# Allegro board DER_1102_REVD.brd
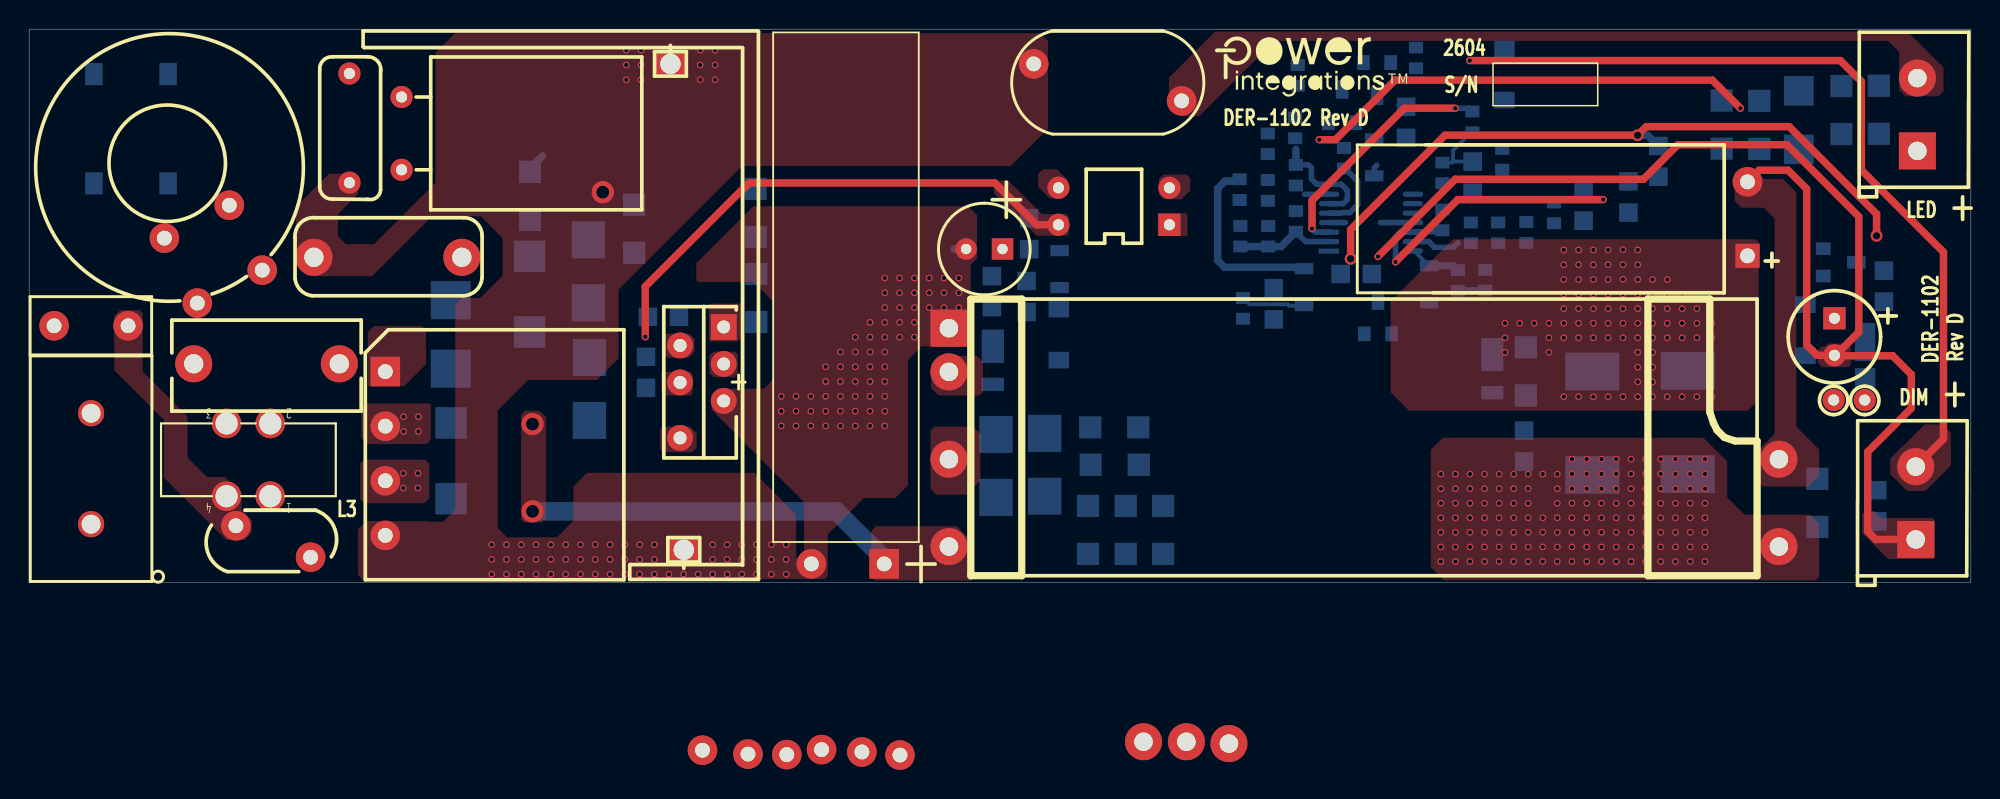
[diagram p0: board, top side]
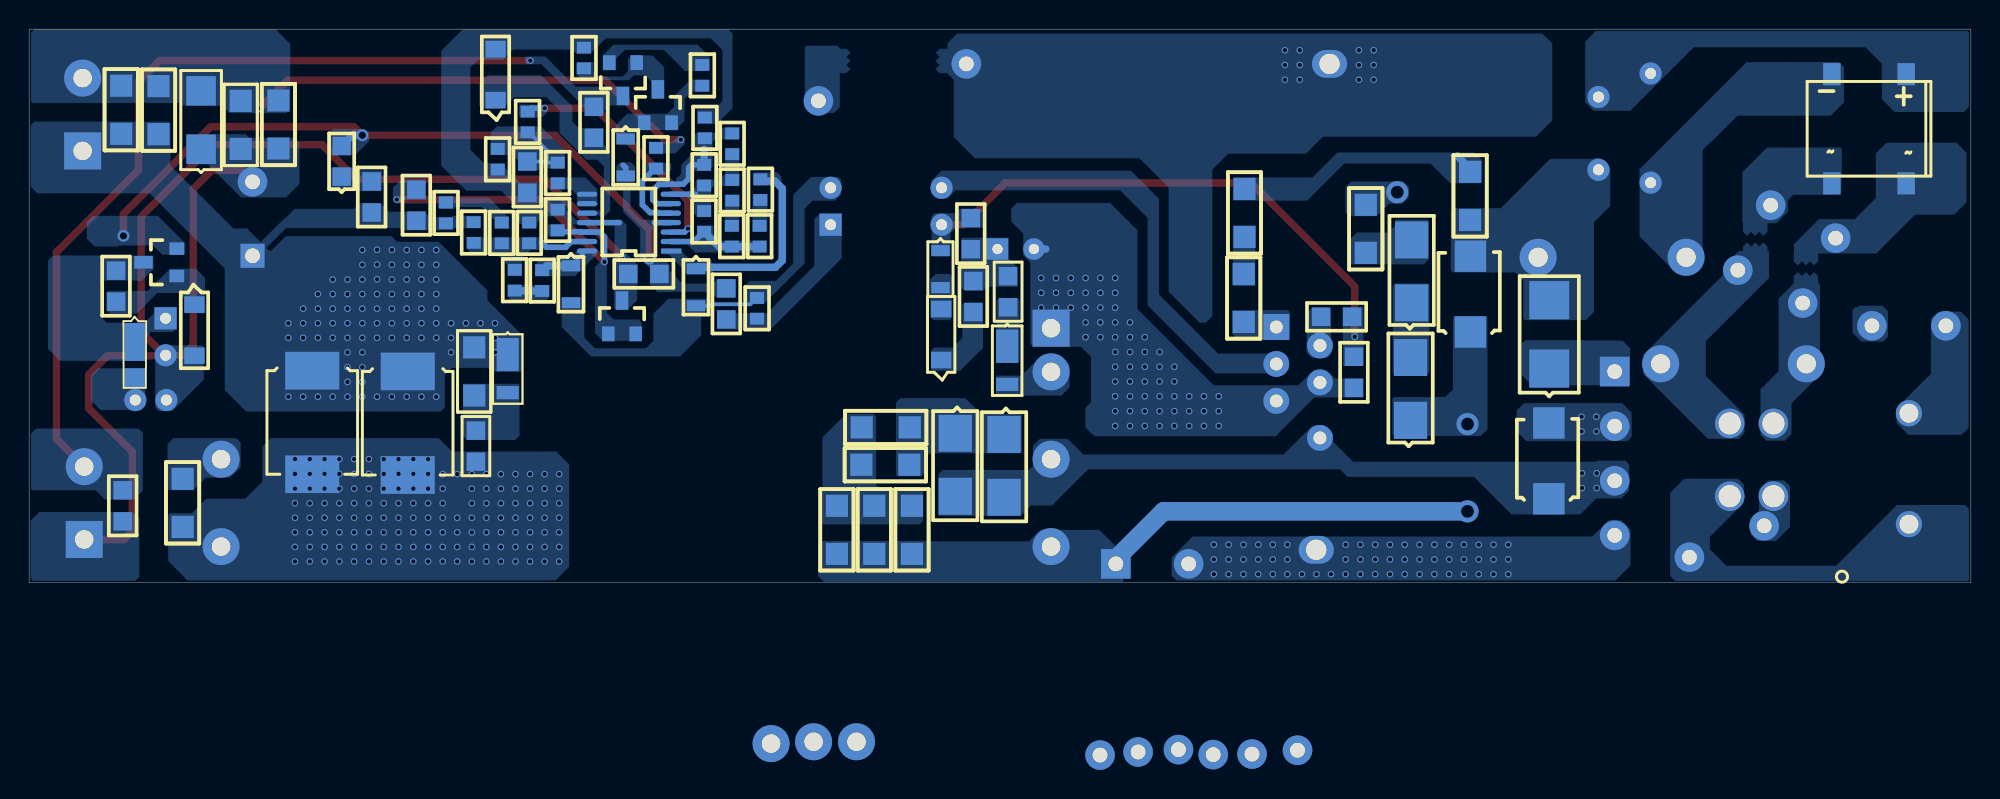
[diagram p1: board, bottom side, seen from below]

Outline 133.35 x 38 mm; copper layers: TOP, BOTTOM. Coordinates in mm from the lower left corner of the outline.
Outline path: 0,38 0,0 133.35,0 133.35,38 0,38

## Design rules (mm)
constraint set DEFAULT: min track width 0.508

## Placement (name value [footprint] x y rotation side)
BR1  MSB30M-13  [PISMD_4SMD_DI]  7 31.15 0 bottom
C1  220 pF  [PISMC0805]  102.67 8.29 90 bottom
C2  1000 pF  [PISMC1206]  72.72 1.96 90 bottom
C3  330 uF  [PIPOLCAPCLYD10MM040]  118.01 22.43 90 top
C5  15 uF  [PIPOLCAPCLYD10X35D040]  53.72 1.27 0 top
C7  68 nF  [PI_NP_CAP_RAD9P8X4P2X7P5X0P6]  22 34.95 270 top
C8  22 uf  [PIPOLCAPCLYD248LS098028]  65.6 22.89 180 top
C9  220 nF  [PI_NP_CAP_RAD470X220LS400D40]  29.72 22.33 180 top
C10  0.47 uF  [PISMC0805]  42.37 15.49 270 bottom
C11  2.2 nF  [PINPYCAPRAD540X290LS400040]  68.99 35.61 0 top
C15  100 uF  [PIPOLCAPCYLD250LS100030]  123.98 18.14 270 top
C21  10 uF  [PISMC0805]  90.07 21.18 0 bottom
C30  1 uF  [PISMC0603]  83.13 26.26 90 bottom
C31  100 pF  [PISMC0603]  85.06 30.84 270 bottom
C33  4.7 uF  [PISMC0805]  99.14 26.77 90 bottom
C35  1000 pF  [PISMC0603]  85.09 24.49 270 bottom
C37  1000 pF  [PISMC0805]  126.92 4.19 90 bottom
C38  10 uF  [PISMC1206]  127.03 34.11 270 bottom
C39  1 uF  [PISMC0603]  97.05 25.6 270 bottom
C40  100 pF  [PISMC0603]  100.89 24.71 270 bottom
C41  22 nF  [PISMC0603]  98.12 20.02 90 bottom
C42  10 uF  [PISMC1206]  124.46 34.09 270 bottom
C43  100 pF  [PISMC1206]  122.81 3.81 90 bottom
CX1  0.15 uF  [PINPXCAPRAD13X6MM040]  11.3 15.01 0 top
D1  PU6JB  [PISMSMB]  34.37 17.2 90 bottom
D2  HS5F  [PISMDO214AB12]  107.35 14.49 270 bottom
D3  HS5F  [PISMDO214AB12]  113.91 14.54 270 bottom
D4  USB260HM3/52T  [PISMDO214AA12]  28.96 14.68 90 bottom
D5  DFLR1200-7  [PISMDDFLR120012]  66.18 16.24 90 bottom
D7  GS1M-LTP  [PISMDO214AC12]  66.4 10.16 270 bottom
D8  GS1M-LTP  [PISMDO214AC12]  69.75 10.24 270 bottom
D9  PU6JB  [PISMSMB]  28.98 5.74 90 bottom
D10  US1B  [PISMDSMA]  121.54 29.74 90 bottom
D11  BAV19WS  [PISMSOD323]  70.76 22.78 270 bottom
D13  BAV16WS-7-F  [PISMSOD323]  87.55 21.54 270 bottom
D14  SS10200HE_R1_00001  [PI_SM_SOD-123HE]  126.09 16.51 270 bottom
D15  SD103CWS-E3-08  [PISMSOD323]  92.38 30.45 270 bottom
D16  BAV16WS-7-F  [PISMSOD323]  96.14 21.74 270 bottom
D17  DFLR1200-7  [PISMDDFLR120012]  100.48 15.67 90 bottom
D18  1N4148WS  [PISMDSOD323]  111.89 27.86 90 bottom
F1  3.15 A  [PI_RST_MICROFUSE]  1.72 17.62 0 top
FL1  Hole_30mils  [PI_HOLE_30MIL]  126.06 12.52 0 top
FL2  Hole_30mils  [PI_HOLE_30MIL]  123.93 12.52 0 top
HS_POST1  HS_Post  [PI_HSK_POST]  44.04 35.61 180 top
HS_POST2  HS_Post  [PI_HSK_POST]  44.96 2.24 0 top
J1  TERMINAL BLOCK  [PI_TERM_BLOCK_2PIN_LS200]  129.68 29.63 0 top
J2  CON2  [CONN_1707027_PXC]  4.26 4 90 top
J11  TERMINAL BLOCK  [PI_TERM_BLOCK_2PIN_LS200]  129.57 2.95 0 top
L1  22 mH  [PI_IND_4P_21P5X11MMD041]  9.48 28.79 26.9 top
L2  1 mH  [PICHOKE10P5X14P5D030]  25.58 30.84 270 top
L3  250 uH  [PI_TOROID_CMC4P_V_DER1094]  16.56 5.92 180 top
L4  80 ohm  [PISMR0805]  42.49 18.24 0 bottom
NOREF  -  []  0 38 0 top
NOREF#2  -  []  81.46 37.92 0 top
NOREF#3  -  []  0 0 90 top
Q5  MMBT3906  [PISMSOT23123_1]  92.56 34.59 0 bottom
Q7  FMMT491  [PISMSOT23123_1]  124.31 21.97 90 bottom
R1  100  [PISMR1206]  102.79 12.84 90 bottom
R2  1 M  [PISMR1206]  75.31 1.96 90 bottom
R3  1 M  [PISMR1206]  77.88 1.96 90 bottom
R4  2.40 M  [PISMR1206]  34.39 24.89 90 bottom
R7  20  [PISMR1206]  76.17 10.64 180 bottom
R8  20  [PISMR1206]  76.2 8.08 180 bottom
R9  10  [PISMR0805]  66.12 18.9 90 bottom
R10  6.98 k  [PISMR0805]  68.68 22.89 90 bottom
R13  2.7 M  [PISMR1206]  49.94 21.18 270 bottom
R16  0.2  [PISMR1206]  118.82 29.77 90 bottom
R27  2.40 M  [PISMR1206]  49.89 27.03 270 bottom
R28  270  [PISMR0805]  68.5 18.57 90 bottom
R33  1 k  [PISMR0603]  90.3 29.84 270 bottom
R34  1 k  [PISMR0603]  86.94 30.51 90 bottom
R35  86.6 k  [PISMR0603]  87 27.25 90 bottom
R36  15 k  [PISMR0603]  83.19 23.06 90 bottom
R37  12.1 k  [PISMR0603]  87 25.5 270 bottom
R39  10 k  [PISMR0603]  99.11 32.33 270 bottom
R40  7.5 k  [PISMR0603]  95.25 35.31 90 bottom
R41  6.34 k  [PISMR0603]  87.12 34.11 90 bottom
R42  20 k  [PISMR0805]  94.56 30.53 90 bottom
R47  1 k  [PISMR1206]  41.55 22.63 90 bottom
R48  3.3 k  [PISMR0805]  127.38 21.41 270 bottom
R49  1 k  [PISMR0805]  85.47 20.19 270 bottom
R57  47.5 k  [PISMR0805]  106.76 24.84 90 bottom
R59  0.2  [PISMR1206]  116.23 29.79 90 bottom
R60  1 k  [PISMR0603]  85.06 27.64 270 bottom
R62  15 k  [PISMR0603]  99.01 23.29 90 bottom
R63  10 k  [PISMR0603]  104.72 24.66 90 bottom
R64  205 k  [PISMR0603]  102.82 24.74 270 bottom
R65  249 k  [PISMR0603]  100 21.46 270 bottom
R66  20 k  [PISMR0603]  97.05 28.83 270 bottom
R67  3.32 k  [PISMR0603]  83.36 18.11 90 bottom
R68  100  [PISMR0805]  109.83 25.4 90 bottom
R69  3 M  [PISMR0603]  101.17 29.77 270 bottom
RV1  300 Vac  [PIDISC350X160LS210X140040]  13.64 4.55 0 top
T1  EDR4110  [PI_BOBBIN_EDR4110_9P_6X3]  91.67 9.96 0 top
T2  EPC17  [PI_BOBBIN_EPC17_4X6_10P]  24.46 14.48 0 top
U1  LTV817A  [PI_DIP4]  78.31 24.56 90 top
U2  TNY5075E  [PIICESIP76TH]  47.7 17.54 270 top
U4  ADA4522-4ARUZ-RL  [PI_SM_14TSSOP]  89.28 22.76 90 bottom
U6  LMV431AIMF  [PISMSOT23132]  89.23 31.57 180 bottom
U9  LM431BIM3/NOPB  [PISMSOT23123]  91.69 17.07 180 bottom
VR2  MMSZ5241C-E3-08  [PI_SM_SOD-123_12]  70.71 15.27 90 bottom
VR3  BZG04-200-HM3-08  [PISMDO214AC12]  38.48 11.13 90 bottom
VR4  BZG04-200-HM3-08  [PISMDO214AC12]  38.4 19.2 90 bottom
VR6  MMSZ5242B-7-F  [PI_SM_SOD-123_12]  101.32 33.12 90 bottom
VR7  MMSZ5242B-7-F  [PI_SM_SOD-123_12]  122 19.08 270 bottom

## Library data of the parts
BR1 = DIODE BRIDGE_+~-~
C1 C10 C21 C33 C37 = CAP NP: alternate symbols: (Unisem_RMCF0805UL)
C2 C7 = CAP NP
C3 = CAP POL: alternate symbols: (pipolcapcyld400ls2000401000h)
C5 = CAP POL: alternate symbols: (pipolcapclyd10x35D040H)
C8 = CAP POL: alternate symbols: (pipolcapclyd248ls098028_h)
C9 = CAP NP: alternate symbols: (pi_np_cap_rad470x220ls400d40_h)
C11 = CAP NP: alternate symbols: (pinpycaprad540x290ls400040h)
C15 = CAP POL: alternate symbols: (pipolcapcyld250ls100030h)
C30 = CAP NP: alternate symbols: (Unisem_RMCF0603UL,pismc0603_1)
C31 C39 C41 = CAP NP: alternate symbols: (Unisem_RMCF0603UL)
C35 C40 = CAP NP: alternate symbols: (Unisem_RMCF0603UL); room: 3
C38 C42 = CAP NP: alternate symbols: (pismc1206_1)
C43 = CAP NP: room: 3
CX1 = CAP NP: alternate symbols: (pinpxcaprad13x6x12Hmm040)
D1-D5 D7-D11 D17 D18 = DIODE
D13 D16 = DIODE: alternate symbols: (SOD323_UL_IPC,pismsod323_1)
D14 = DIODE SCHOTTKY
D15 = DIODE SCHOTTKY: alternate symbols: (SOD323_UL_IPC,pismsod323_1)
F1 = FUSE: alternate symbols: (pirstmicrofusehoz)
FL1 FL2 = FlyingLead: room: 3
HS_POST1 HS_POST2 = HS_POST
J1 J11 = CON2
J2 = CON2: User Part Number: PN; Tolerance: TOL
L1 = CMC_ 4P_12_34: alternate symbols: (pi_ind_4p_21p5x11mmd041H)
L2 = INDUCTOR: alternate symbols: (pichoke10p5x14p5d030H)
L3 = TORRID 4P_12_43a: alternate symbols: (pi_torid_CMC4p_H)
L4 = INDUCTOR_BEAD_2
Q5 = PNP_BEC
Q7 = NPN_BEC
R1-R4 R7 R8 R13 R16 R27 R47 R59 = R
R9 R10 R28 R42 R48 R49 R68 = R: alternate symbols: (Unisem_RMCF0805UL)
R33-R37 R39-R41 R64-R66 = R: alternate symbols: (Unisem_RMCF0603UL)
R57 = R: alternate symbols: (Unisem_RMCF0805UL); room: 3
R60 R62 R63 R67 R69 = R: alternate symbols: (Unisem_RMCF0603UL); room: 3
RV1 = VARISTOR: alternate symbols: (pi_disc_354x220_ls220x10_040_h,pidisc350x160ls210x140040SF)
T1 = BEQ20_9P
T2 = BEPC_17_10P
U1 = OPTO_A_B
U2 = TinySwitch-5E
U4 = TL084_Hetero
U6 = TL431/SOT-23_RCA
U9 = TL431/SOT-23_CAR
VR2-VR4 VR6 VR7 = DIODE_ZENER

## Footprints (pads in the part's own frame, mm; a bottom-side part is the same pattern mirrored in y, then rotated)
CONN_1707027_PXC
  round 1.803 hole 1.295: 1(0,0) 2(7.62,0)
PI_BOBBIN_EDR4110_9P_6X3
  rect 2.54x2.54 hole 1.27: 1(-28.5,7.5)
  round 2.54 hole 1.27: 2(-28.5,4.5) 3(-9.271,-21.031) 4(-28.5,-1.5) 5(-15.138,-20.904) 6(-28.5,-7.5) 7(28.5,-7.5) 8(-12.192,-20.904) 9(28.5,-1.5)
PI_BOBBIN_EPC17_4X6_10P
  rect 2.032x2.032 hole 1.016: 1(0,0)
  round 2.032 hole 1.016: 2(0,-3.75) 3(0,-7.5) 4(0,-11.25) 5(35.346,-26.342) 6(32.73,-26.128) 7(29.961,-25.964) 8(27.573,-26.309) 9(24.906,-26.273) 10(21.782,-26.008)
PI_DIP4
  rect 1.524x1.524 hole 0.762: 1(0,0)
  round 1.524 hole 0.762: 2(2.54,0) 3(2.54,7.62) 4(0,7.62)
PI_HOLE_30MIL
  round 1.524 hole 0.762: 1(0,0)
PI_HSK_POST
  oval 2.413x1.905 hole 1.397: 1(0,0)
PI_IND_4P_21P5X11MMD041
  round 2.032 hole 1.016: 1(-2.5,-4.5) 2(-2.5,-9.5) 3(2.5,-4.5) 4(2.5,-9.5)
PI_NP_CAP_RAD9P8X4P2X7P5X0P6
  round 1.524 hole 0.762: 1(0,0) 2(7.5,0)
PI_NP_CAP_RAD470X220LS400D40
  round 2.54 hole 1.321: 1(0,0) 2(10.16,0)
PI_RST_MICROFUSE
  round 2.032 hole 1.016: 1(0,0) 2(5.08,0)
PI_SM_14TSSOP
  rect 0.356x1.397 smd: 1(-0.005,-0.03)
  oval 0.356x1.397 smd: 2(0.65,0) 3(1.3,0) 4(1.95,0) 5(2.6,0) 6(3.25,0) 7(3.9,0) 8(3.9,5.75) 9(3.25,5.75) 10(2.6,5.75) 11(1.95,5.75) 12(1.3,5.75) 13(0.65,5.75) 14(0,5.75)
PI_SM_SOD-123_12
  rect 1.143x1.397 smd: 1(0,0) 2(3.505,0)
PI_SM_SOD-123HE
  rect 2.6x1.4 smd: 1(0,0)
  rect 1.3x1.4 smd: 2(2.45,0)
PI_TERM_BLOCK_2PIN_LS200
  rect 2.54x2.54 hole 1.27: 1(0,0)
  round 2.54 hole 1.27: 2(0,5.001)
PI_TOROID_CMC4P_V_DER1094
  round 2.032 hole 1.524: 1(0,0) 2(0,-5) 3(3,-5) 4(3,0)
PICHOKE10P5X14P5D030
  round 1.524 hole 0.762: 1(-2.5,0) 2(2.5,0)
PIDISC350X160LS210X140040
  round 2.032 hole 1.016: 1(0.559,-0.66) 2(5.69,-2.819)
PIICESIP76TH
  rect 1.778x1.778 hole 0.889: 1(0,0)
  round 1.778 hole 0.889: 2(1.27,-2.997) 3(2.54,0) 4(3.81,-2.997) 5(5.08,0) 7(7.62,-2.997)
PINPXCAPRAD13X6MM040
  round 2.54 hole 1.321: 1(0,0) 2(10,0)
PINPYCAPRAD540X290LS400040
  round 2.032 hole 1.016: 1(0,0) 2(10.16,-2.54)
PIPOLCAPCLYD10MM040
  rect 1.651x1.651 hole 1.016: 1(0,0)
  round 2.032 hole 1.016: 2(5.08,0)
PIPOLCAPCLYD10X35D040
  rect 2.032x2.032 hole 1.016: 1(5,0)
  round 2.032 hole 1.016: 2(0,0)
PIPOLCAPCLYD248LS098028
  rect 1.473x1.473 hole 0.711: 1(-1.25,0)
  round 1.473 hole 0.711: 2(1.25,0)
PIPOLCAPCYLD250LS100030
  rect 1.524x1.524 hole 0.762: 1(0,0)
  round 1.524 hole 0.762: 2(2.54,0)
PISMC0603
  rect 0.813x0.965 smd: 1(0,0) 2(1.422,0)
PISMC0805
  rect 1.27x1.27 smd: 1(0,0) 2(2.134,0)
PISMC1206
  rect 1.524x1.524 smd: 1(0,0) 2(3.302,0)
PISMD_4SMD_DI
  rect 1.2x1.52 smd: 1(-2.55,-3.75) 2(-2.55,3.75) 3(2.55,-3.75) 4(2.55,3.75)
PISMDDFLR120012
  rect 2.286x1.524 smd: 1(-0.025,0)
  rect 0.914x1.524 smd: 2(-2.642,0)
PISMDO214AA12
  rect 2.616x2.743 smd: 1(0,0) 2(4.699,0)
PISMDO214AB12
  rect 2.591x3.708 smd: 1(0,0) 2(7.112,0)
PISMDO214AC12
  rect 2.54x2.286 smd: 1(0,0) 2(4.318,0)
PISMDSMA
  rect 2.032x2.032 smd: 1(0,0) 2(4.013,0)
PISMDSOD323
  rect 1.27x1.27 smd: 1(0,0) 2(2.108,0)
PISMR0603
  rect 0.813x0.965 smd: 1(0,0) 2(1.422,0)
PISMR0805
  rect 1.27x1.27 smd: 1(0,0) 2(2.134,0)
PISMR1206
  rect 1.524x1.524 smd: 1(0,0) 2(3.302,0)
PISMSMB
  rect 2.159x2.159 smd: 1(0,0) 2(5.207,0)
PISMSOD323
  rect 0.762x1.27 smd: 1(0,0) 2(2.54,0)
PISMSOT23123
  rect 0.864x1.016 smd: 1(-1.88,0) 3(0,0)
  rect 0.864x1.27 smd: 2(-0.94,2.286)
PISMSOT23123_1
  rect 0.864x1.016 smd: 1(-0.93,-1.1) 2(0.95,-1.1)
  rect 0.864x1.27 smd: 3(0.01,1.186)
PISMSOT23132
  rect 0.864x1.016 smd: 1(-1.88,0) 2(0,0)
  rect 0.864x1.27 smd: 3(-0.94,2.286)

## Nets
GND: C3.2 C15.2 C21.2 C33.1 C37.1 C39.1 C43.2 D10.1 FL2.1 J11.1 R16.1 R34.2 R40.2 R59.1 R62.2 R69.2 T1.9 U4.11 U9.2 VR6.2 VR7.2
VO: C3.1 C38.2 C42.2 D2.1 D3.1 D17.1 J1.1 R1.2 R57.1 R63.1 R64.1 R68.1
N9537943: BR1.1 C7.1 L2.1
N9537951: BR1.3 C5.2 C7.2 C8.2 C9.2 C10.2 C11.1 HS_POST1.1 HS_POST2.1 R47.2 T1.1 T2.4 U2.4 U2.5
N9538078: C9.1 D1.2 D4.2 L2.2 R4.1
N9539529: F1.1 J2.2
N9539533: CX1.1 L1.2 L3.3
N9539579: CX1.2 L1.4 L3.2
N9541022: BR1.2 L1.1
N9541042: BR1.4 L1.3
N9541964: C2.1 C5.1 D1.1 R2.1 R3.1 T1.6 VR3.1
N9542431: R4.2 R27.1
N9542586: D4.1 T2.1
N9542750: D7.2 D8.2 D9.1 T1.4 T2.3 U2.7
N9542850: D7.1 D8.1 R7.2 R8.2
N9544139: U1.3(E) U2.3
N9545267: C8.1 R9.2 R10.1 R28.2
N9545282: D5.2 T1.2
N9545292: D5.1 R9.1
N9546383: C1.1 C43.1 D2.2 D3.2 T1.7
N9546628: C1.2 D17.2 R1.1
N9547867: C11.2 C38.1 C42.1 D10.2 J1.2 R16.2 R33.1 R59.2
N9549268: C2.2 R2.2 R3.2 R7.1 R8.1
N9550559: L4.2 U2.2
N9550563: C10.1 D11.1 L4.1 R10.2 U1.4
N9560533: R13.2 U2.1
N9561535: D9.2 T2.2
N14039798: J2.1 L3.1 RV1.2
N14052600: F1.2 L3.4 RV1.1
N14052856: R13.1 R27.2
N14062269: D11.2 VR2.2
N14069124: VR3.2 VR4.1
N14069146: R47.1 VR4.2
N14074284: C21.1 D15.2 D18.2 Q7.2(EMITTER) R49.1 U4.4
N14074308: Q5.2(EMITTER) R41.2
N14074340: D15.1 R41.1 U6.1(VREF) U6.2
N14074422: Q5.1 R40.1 U6.3
N14074628: R39.1 U4.3
N14074640: R42.1 U4.10 VR6.1
N14074656: C37.2 J11.2 Q5.3 R42.2
N14074980: R33.2 U4.5
N14074984: C31.2 R35.1 R37.1 R60.1 U4.7
N14075000: C31.1 R34.1 R35.2 U4.6
N14077546: C15.1 D14.1 Q7.3 R48.1
N14077592: Q7.1 R48.2 VR7.1
N14078876: R49.2 R67.1 U1.1
N14079186: D13.2 D16.2 R67.2 U1.2
N14082476: C35.2 R36.1 R37.2 U4.2
N14152194: C35.1 R60.2
N14168566: D14.2 FL1.1
N14175933: C33.2 R39.2 R66.1 R69.1
N14177524: R66.2 U4.8 U4.9
N14180613: C41.2 D16.1 U4.14(4OUT)
N14180712: C39.2 R57.2 U4.12 U9.1 U9.3(VREF)
N14181517: C30.2 D13.1 U4.1
N14182326: C30.1 R36.2
N14183243: C40.1 R63.2
N14183547: C40.2 R62.1 R64.2 R65.1 U4.13
N14184679: C41.1 R65.2
N14215361: R28.1 VR2.1
N14231123: D18.1 R68.2

Pads without a net: T1 3 5 8; T2 5 6 7 8 9 10

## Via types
v1: diameter 0.457, hole 0.305, TOP to BOTTOM, 378 vias
v2: diameter 0.813, hole 0.508, TOP to BOTTOM, 3 vias
v3: diameter 1.524, hole 0.889, TOP to BOTTOM, 3 vias

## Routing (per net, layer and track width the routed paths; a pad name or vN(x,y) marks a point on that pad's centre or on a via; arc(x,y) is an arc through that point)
GND: length 89.9
  TOP w0.381: 124.71,15.57 124.03,15.57
  TOP w0.508: 124.71,15.57 127.97,15.57 129.26,14.27 129.26,11.96 126.26,8.97 126.26,3.51 126.82,2.95 J11.1 ; v1(92.63,22.38) 97.94,27.69 110.86,27.69 113.23,30.06 120.71,30.06 125.65,25.12 125.65,17.19 124.03,15.57 124,15.6 C15.2 122.78,15.6 122.07,16.31 122.07,27.03 120.79,28.31 118.81,28.31 C3.2
  BOTTOM w0.381: U4.11 92.81,24.71
VO:
  vias: v1(101.36,17.8) v1(101.36,16.8) v1(101.36,15.8) v1(102.36,17.8) v1(103.36,17.8) v1(104.37,17.8) v1(104.37,16.8) v1(104.37,15.8) v1(105.39,22.83) v1(105.39,21.81) v1(105.39,20.8) v1(105.39,19.8) v1(105.39,18.8) v1(105.39,17.8) v1(105.39,16.8) v1(105.39,12.75) v1(106.41,22.83) v1(106.41,21.81) v1(106.41,20.8) v1(106.41,19.8) v1(106.41,18.8) v1(106.41,17.8) v1(106.41,16.8) v1(106.41,12.75) v1(107.42,22.83) v1(107.42,21.81) v1(107.42,20.8) v1(107.42,19.8) v1(107.42,18.8) v1(107.42,17.8) v1(107.42,16.8) v1(107.42,12.75) v1(108.44,22.83) v1(108.44,21.81) v1(108.44,20.8) v1(108.44,19.8) v1(108.44,18.8) v1(108.44,17.8) v1(108.44,16.8) v1(108.44,12.75) v1(109.45,22.85) v1(109.45,21.83) v1(109.45,20.81) v1(109.45,19.8) v1(109.45,18.8) v1(109.45,17.8) v1(109.45,16.8) v1(109.45,12.75) v1(110.47,22.83) v1(110.47,21.81) v1(110.47,20.8) v1(110.47,19.8) v1(110.47,18.8) v1(110.47,17.8) v1(110.47,16.8) v1(110.47,15.8) v1(110.47,14.78) v1(110.47,13.77) v1(110.47,12.75) v1(111.49,20.8) v1(111.49,19.8) v1(111.49,18.8) v1(111.49,17.8) v1(111.49,16.8) v1(111.49,15.8) v1(111.49,14.78) v1(111.49,13.77) v1(111.49,12.75) v1(112.5,20.8) v1(112.5,19.8) v1(112.5,18.8) v1(112.5,17.8) v1(112.5,16.8) v1(112.5,12.75) v1(113.52,19.8) v1(113.52,18.8) v1(113.52,17.8) v1(113.52,16.8) v1(113.52,12.75) v1(114.53,18.8) v1(114.53,17.8) v1(114.53,16.8) v1(114.53,12.75) v1(115.55,17.8) v1(115.55,16.8) v1(115.55,12.75)
N9537951: length 0.8
  BOTTOM w0.508: 63.53,22.89 C8.2
  vias: v1(31.77,2.59) v1(31.77,1.57) v1(31.77,0.56) v1(32.78,2.59) v1(32.78,1.57) v1(32.78,0.56) v1(33.8,2.59) v1(33.8,1.57) v1(33.8,0.56) v1(34.81,2.59) v1(34.81,1.57) v1(34.81,0.56) v1(35.83,2.59) v1(35.83,1.57) v1(35.83,0.56) v1(36.85,2.59) v1(36.85,1.57) v1(36.85,0.56) v1(37.86,2.59) v1(37.86,1.57) v1(37.86,0.56) v1(38.88,2.59) v1(38.88,1.57) v1(38.88,0.56) v1(39.89,2.59) v1(39.89,1.57) v1(39.89,0.56) v1(40.91,2.59) v1(40.91,1.57) v1(40.91,0.56) v1(41.01,36.55) v1(41.01,35.53) v1(41.01,34.52) v1(41.93,2.59) v1(41.93,1.57) v1(41.93,0.56) v1(42.03,36.55) v1(42.03,35.53) v1(42.03,34.52) v1(42.94,2.59) v1(42.94,1.57) v1(42.94,0.56) v1(43.94,0.56) v1(44.94,0.56) v1(45.94,0.56) v1(46.09,36.55) v1(46.09,35.53) v1(46.09,34.52) v1(46.94,2.59) v1(46.94,1.57) v1(46.94,0.56) v1(47.11,36.55) v1(47.11,35.53) v1(47.11,34.52) v1(47.94,2.59) v1(47.94,1.57) v1(47.94,0.56) v1(48.94,2.59) v1(48.94,1.57) v1(48.94,0.56) v1(49.96,2.59) v1(49.96,1.57) v1(49.96,0.56) v1(50.97,2.59) v1(50.97,1.57) v1(50.97,0.56) v1(51.65,12.78) v1(51.65,11.76) v1(51.65,10.74) v1(51.99,2.59) v1(51.99,1.57) v1(51.99,0.56) v1(52.67,12.78) v1(52.67,11.76) v1(52.67,10.74) v1(53.69,12.78) v1(53.69,11.76) v1(53.69,10.74) v1(54.7,14.81) v1(54.7,13.79) v1(54.7,12.78) v1(54.7,11.76) v1(54.7,10.74) v1(55.72,15.82) v1(55.72,14.81) v1(55.72,13.79) v1(55.72,12.78) v1(55.72,11.76) v1(55.72,10.74) v1(56.73,16.84) v1(56.73,15.82) v1(56.73,14.81) v1(56.73,13.79) v1(56.73,12.78) v1(56.73,11.76) v1(56.73,10.74) v1(57.75,17.86) v1(57.75,16.84) v1(57.75,15.82) v1(57.75,14.81) v1(57.75,13.79) v1(57.75,12.78) v1(57.75,11.76) v1(57.75,10.74) v1(58.77,20.9) v1(58.77,19.89) v1(58.77,18.87) v1(58.77,17.86) v1(58.77,16.84) v1(58.77,15.82) v1(58.77,14.81) v1(58.77,13.79) v1(58.77,12.78) v1(58.77,11.76) v1(58.77,10.74) v1(59.78,20.9) v1(59.78,19.89) v1(59.78,18.87) v1(59.78,17.86) v1(59.78,16.84) v1(60.8,20.9) v1(60.8,19.89) v1(60.8,18.87) v1(60.8,17.86) v1(60.8,16.84) v1(61.81,20.9) v1(61.81,19.89) v1(61.81,18.87) v1(62.83,20.9) v1(62.83,19.89) v1(62.83,18.87) v1(63.85,20.9) v1(63.85,19.89) v1(63.85,18.87) v3(39.4,26.8)
N9541964: length 26
  BOTTOM w1.27: v3(34.57,4.88) 55.45,4.88 59.05,1.27
  vias: v3(34.57,10.87)
N9542431: length 1.4
  BOTTOM w0.508: R4.2 34.39,28.42 35.26,29.29
N9542750:
  vias: v1(25.69,7.49) v1(25.69,6.48) v1(26.71,7.49) v1(26.71,6.48)
N9546383:
  vias: v1(96.95,7.43) v1(96.95,6.43) v1(96.95,5.43) v1(96.95,4.43) v1(96.95,3.43) v1(96.95,2.43) v1(96.95,1.43) v1(97.95,7.43) v1(97.95,6.43) v1(97.95,5.43) v1(97.95,4.43) v1(97.95,3.43) v1(97.95,2.43) v1(97.95,1.43) v1(98.95,7.43) v1(98.95,6.43) v1(98.95,5.43) v1(98.95,4.43) v1(98.95,3.43) v1(98.95,2.43) v1(98.95,1.43) v1(99.95,7.43) v1(99.95,6.43) v1(99.95,5.43) v1(99.95,4.43) v1(99.95,3.43) v1(99.95,2.43) v1(99.95,1.43) v1(100.95,7.43) v1(100.95,6.43) v1(100.95,5.43) v1(100.95,4.43) v1(100.95,3.43) v1(100.95,2.43) v1(100.95,1.43) v1(101.95,7.43) v1(101.95,6.43) v1(101.95,5.43) v1(101.95,4.43) v1(101.95,3.43) v1(101.95,2.43) v1(101.95,1.43) v1(102.95,7.43) v1(102.95,6.43) v1(102.95,5.43) v1(102.95,4.43) v1(102.95,3.43) v1(102.95,2.43) v1(102.95,1.43) v1(103.95,7.43) v1(103.95,4.43) v1(103.95,3.43) v1(103.95,2.43) v1(103.95,1.43) v1(104.95,7.43) v1(104.95,6.43) v1(104.95,5.43) v1(104.95,4.43) v1(104.95,3.43) v1(104.95,2.43) v1(104.95,1.43) v1(105.95,8.47) v1(105.95,7.45) v1(105.95,6.43) v1(105.95,5.43) v1(105.95,4.43) v1(105.95,3.43) v1(105.95,2.43) v1(105.95,1.43) v1(106.97,8.47) v1(106.97,7.45) v1(106.97,6.43) v1(106.97,5.43) v1(106.97,4.43) v1(106.97,3.43) v1(106.97,2.43) v1(106.97,1.43) v1(107.98,8.47) v1(107.98,7.45) v1(107.98,6.43) v1(107.98,5.43) v1(107.98,4.43) v1(107.98,3.43) v1(107.98,2.43) v1(107.98,1.43) v1(109,8.47) v1(109,7.45) v1(109,6.43) v1(109,5.43) v1(109,4.43) v1(109,3.43) v1(109,2.43) v1(109,1.43) v1(110.01,8.47) v1(110.01,7.45) v1(110.01,6.43) v1(110.01,5.43) v1(110.01,4.43) v1(110.01,3.43) v1(110.01,2.43) v1(110.01,1.43) v1(111.03,8.47) v1(111.03,7.45) v1(111.03,6.43) v1(111.03,5.43) v1(111.03,4.43) v1(111.03,3.43) v1(111.03,2.43) v1(111.03,1.43) v1(112.05,8.47) v1(112.05,7.45) v1(112.05,6.43) v1(112.05,5.43) v1(112.05,4.43) v1(112.05,3.43) v1(112.05,2.43) v1(112.05,1.43) v1(113.06,8.47) v1(113.06,7.45) v1(113.06,6.43) v1(113.06,5.43) v1(113.06,4.43) v1(113.06,3.43) v1(113.06,2.43) v1(113.06,1.43) v1(114.08,8.47) v1(114.08,7.45) v1(114.08,6.43) v1(114.08,5.43) v1(114.08,4.43) v1(114.08,3.43) v1(114.08,2.43) v1(114.08,1.43) v1(115.09,8.47) v1(115.09,7.45) v1(115.09,6.43) v1(115.09,5.43) v1(115.09,4.43) v1(115.09,3.43) v1(115.09,2.43) v1(115.09,1.43)
N9547867: length 31.4
  TOP w0.508: v1(88.6,30.4) 89.71,30.4 93.8,34.49 115.6,34.49 v1(117.53,32.56)
N9550563: length 36
  TOP w0.508: v1(42.32,16.87) 42.32,20.32 49.02,27.03 49.05,27.03 49.45,27.43 66.32,27.43 69.19,24.56 U1.4
N9561535:
  vias: v1(25.72,11.38) v1(25.72,10.36) v1(26.74,11.38) v1(26.74,10.36)
N14074284: length 48.7
  TOP w0.508: v2(126.87,23.8) 126.87,25.3 120.87,31.3 111.06,31.3 v2(110.46,30.71) 97.23,30.71 90.75,24.23 v2(90.75,22.23)
  BOTTOM w0.381: 92.56,28.65 92.38,28.47 D15.2 ; U4.4 90.4,24.71
  BOTTOM w0.508: v2(110.46,30.71) 111.15,30.71 D18.2
N14074628: length 16.9
  TOP w0.508: v1(88.1,24.3) 88.1,26.23 94.44,32.56 v1(97.94,32.56)
  BOTTOM w0.381: U4.3 88.34,24.06 v1(88.1,24.3) ; R39.1 98.88,32.56 v1(97.94,32.56)
N14074656: length 57.1
  TOP w0.508: v1(98.93,35.84) 124.38,35.84 125.83,34.39 125.83,28.32 131.47,22.68 131.47,9.85 J11.2
N14074980: length 5.1
  BOTTOM w0.381: U4.5 90.08,25.36 90.12,25.39 90.7,25.39 91.24,25.93 91.24,27.56 90.37,28.42 R33.2
N14074984: length 1.7
  BOTTOM w0.381: U4.7 87.59,26.66
N14075000: length 7.8
  BOTTOM w0.381: U4.6 90.25,26.01 90.53,26.29 90.53,26.92 90.12,27.33 90.08,27.33 90.08,27.33 89.58,27.33 89.57,27.34 88.43,27.34 88.06,27.71 88.06,28.47 87.86,28.68 R35.2
  BOTTOM w0.508: 87,29.74 R35.2
N14079186: length 4.4
  BOTTOM w0.254: 83.39,19.53 83.82,19.1 86.44,19.1 86.54,19 D13.2
N14082476: length 6.8
  BOTTOM w0.381: R37.2 87.67,23.41 U4.2
  BOTTOM w0.508: R37.2 85.98,23.06 C35.2 R36.1
N14175933: length 4.7
  BOTTOM w0.254: 97.79,28.91 97.76,28.91 97.69,28.83 R66.1 ; 97.79,28.91 C33.2 ; 97.79,28.91 97.79,29.67 99.03,30.91 R39.2
N14177524: length 0.1
  BOTTOM w0.254: R66.2 96.98,27.41
N14180613: length 3.6
  BOTTOM w0.254: D16.1 95.12,22.76 U4.14
  BOTTOM w0.508: C41.2 97.82,21.74 D16.1
N14180712: length 21.2
  TOP w0.508: v1(108.1,26.29) 98.11,26.29 v1(93.84,22.01)
  BOTTOM w0.381: v1(93.84,22.01) 93.84,23.73 94.16,24.06 U4.12 95.47,24.06 95.5,24.09 96.96,24.09 C39.2
N14181517: length 12.9
  BOTTOM w0.508: C30.2 83.01,27.56 82.13,27.56 81.62,27.05 81.62,22.11 82.09,21.64 87.45,21.64 D13.1
N14183547: length 3.9
  BOTTOM w0.254: 98.15,23.29 97.87,23.01 97.8,23.01
  BOTTOM w0.381: U4.13 96.12,23.41 96.49,23.04 96.49,23.01 97.8,23.01 98.08,23.29 98.15,23.29
N14184679: length 2.8
  BOTTOM w0.254: 99.14,20.04 99.11,20.02
  BOTTOM w0.381: R65.2 99.07,20.04 99.05,20.02
  BOTTOM w0.508: 99.11,20.02 99.97,20.02 R65.2 ; C41.1 99.05,20.02

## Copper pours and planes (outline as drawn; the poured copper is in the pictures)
GND on TOP: 127.18,4.42 130.71,4.42 130.89,4.24 130.89,1.73 130.76,1.6 127.66,1.6 125.88,3.38 125.88,4.67 126.11,4.9 126.7,4.9
GND on TOP: 118.64,8.97 119.86,10.19 119.86,24.99 119.13,25.73 117.6,25.73 117.12,26.21 117.12,28.12 117.42,28.42 118.44,28.42 119.15,27.71 120.45,27.71 121.36,26.8 121.36,10.69 122.94,9.12 122.94,7.34 122.17,6.58 119.08,6.58 118.64,7.01
GND on TOP: 123.55,16.41 124.87,16.41 125.09,16.18 125.09,14.96 124.92,14.78 123.14,14.78 122.83,15.09 122.83,15.95 123.09,16.21 123.34,16.21
GND on BOTTOM: 121.46,16.28 124.33,16.28 124.69,15.93 124.69,12.01 124.43,11.76 123.52,11.76 121.36,13.92 121.36,16.15 121.46,16.26
GND on BOTTOM: 118.8,26.44 115.7,26.44 114.78,27.36 114.78,30.15 115.16,30.53 118.24,30.53 118.49,30.78 122.53,30.78 122.56,30.76 122.56,28.82 121.17,28.82
GND on BOTTOM: 85.32,37.97 103.58,37.97 105.05,36.5 105.05,28.63 103.33,26.9 100.94,26.9 99.72,25.68 99.72,24.74 99.26,24.28 98.63,24.28 98.45,24.46 98.45,24.71 98.02,25.15 96.67,25.15 96.06,24.54 94.44,24.54 94.31,24.66 94.31,24.82 94.39,24.89 95.78,24.89 96.44,25.55 96.44,26.09 96.72,26.37 97.94,26.37 98.25,26.67 98.25,27.28 98.42,27.46 99.64,27.46 100.66,28.47 100.66,28.73 100.72,28.79 102.12,28.79 103.05,29.72 103.05,35.38 102.54,35.89 100.81,35.89 100.1,36.6 96.06,36.6 95.78,36.32 94.79,36.32 93.75,37.36 86.54,37.36 85.74,36.56 85.74,33.06 86.31,32.49 87.48,32.49 87.48,31.52 87.45,31.5 86.11,31.5 85.04,32.56 85.04,37.69
GND on BOTTOM: 133.25,4.24 133.25,0.28 133.07,0.1 126.06,0.1 125.78,0.38 125.78,4.37 126.24,4.83 132.66,4.83
GND on BOTTOM: 91.59,21.84 91.59,19.38 92.25,18.72 93.07,18.72 93.17,18.82 93.17,22.25 93.14,22.28 93.14,24.84 93.07,24.92 92.68,24.92 92.33,24.56 92.33,22.58
GND on BOTTOM: 119.13,9.91 123.44,9.91 123.85,9.5 123.85,6.43 123.75,6.32 122.07,6.32 121.21,7.19 119.56,7.19 118.82,7.92 118.82,9.6
VO on TOP: 118.01,11.79 94.77,11.79 93.5,13.06 93.5,19.28 97.79,23.57 118.57,23.57 118.78,23.36 118.78,12.56
VO on BOTTOM: 132.99,31.65 133.25,31.39 133.25,27.18 132.77,26.7 132.74,26.72 125.07,26.72 119.91,21.56 119.91,13.21 118.44,11.73 105.08,11.73 104.8,12.01 104.8,14.25 104.32,14.73 101.85,14.73 101.6,14.48 99.49,14.48 99.42,14.55 99.42,16.92 101.88,19.38 101.88,20.04 105.23,23.39 108.08,23.39 108.46,23.77 115.72,23.77 116.71,22.78 116.87,22.78 118.39,24.31 119.33,24.31 123.65,28.63 123.65,31.55 123.75,31.65
VO on BOTTOM: 102.39,25.17 102.39,24.38 102.44,24.33 104.17,24.33 104.32,24.18 107.8,24.18 107.87,24.26 107.87,24.28 107.92,24.33 115.7,24.33 117.78,22.25 117.98,22.45 117.98,22.83 115.8,25.02 115.75,25.02 115.11,25.65 111.05,25.65 110.67,26.04 109.22,26.04 108.64,25.45 106.1,25.45 106.1,25.37 105.79,25.07 104.34,25.07 104.24,25.17
N9537943 on BOTTOM: 7.24,36.75 6.12,35.64 6.12,34.26 6.11,34.25 6.11,33.19 5.23,32.31 0.48,32.31 0.13,32.66 0.13,37.77 0.23,37.87 25.76,37.87 26.49,37.13 26.49,32.97 25.93,32.41 25.93,32.38 23.39,32.38 19.02,36.75
N9537951 on TOP: 64.67,21.82 64.67,16.21 61.29,16.21 60.35,15.27 60.35,6.65 59.49,5.79 57.33,5.79 54.84,3.3 54.84,1.27 54.2,0.64 53.87,0.64 53.21,1.3 53.21,5.51 46.86,11.86 46.86,12.9 47.27,13.31 50.47,13.31 51.08,13.92 51.08,19.3 49.76,20.62 45.95,20.62 45.82,20.75 45.82,21.92 49.73,25.83 64.49,25.83 65.1,25.22 65.1,22.25
N9537951 on TOP: 69.42,37.72 69.98,37.16 69.98,31.17 67.41,28.6 48.97,28.6 40.47,20.1 40.47,15.38 38.99,13.89 34.26,13.89 32.18,11.81 32.18,3.73 32.82,3.1 36.25,3.1 37.39,4.24 37.39,6.6 38.3,7.52 49.81,7.52 52.68,4.65 52.68,1.75 52.81,1.63 53.06,1.63 53.21,1.78 53.21,2.06 54.58,2.06 54.84,1.8 54.84,0.43 54.62,0.22 22.87,0.22 22.58,0.51 22.58,3.63 23.16,4.22 24.87,4.22 24.88,4.2 27.42,4.2 27.46,4.17 28.42,4.17 29.26,5 29.26,19.1 29.69,19.53 30.99,19.53 32.51,21.06 32.51,23.65 31.01,25.15 27.66,25.15 23.55,21.03 19.13,21.03 18.31,21.84 18.31,25.78 20.6,28.07 22.15,28.07 22.58,27.64 22.58,26.67 21.21,25.3 21.21,23.77 21.74,23.24 23.7,23.24 27.91,27.46 27.91,36.39 29.27,37.74 29.29,37.72
N9537951 on TOP: 45.39,14.45 43.48,14.45 43.41,14.38 43.41,13.16 43.74,12.83 45.42,12.83 45.57,12.98 45.57,14.27
N9537951 on BOTTOM: 9.07,35.74 12.88,35.74 12.89,35.73 15.41,35.73 22.76,28.37 22.76,23.77 20.32,21.34 19.51,21.34 18.41,22.43 18.41,29.72 17.91,30.23 17.86,30.23 16.03,32.05 9.63,32.05 8.71,32.97 8.71,35.38
N9537951 on BOTTOM: 64.59,21.97 64.59,16.38 64.39,16.18 61.11,16.18 61.11,16.15 61.09,16.15 60.43,15.49 60.43,12.37 60.81,11.99 60.81,10.64 60.2,10.03 47.75,10.03 45.09,12.7 41.76,12.7 41.76,14 43.66,14 44.27,14.61 45.11,14.61 46.18,13.54 52.01,13.54 57.24,18.77 57.24,24.19 59.11,26.06 65.51,26.06 65.91,25.65 65.91,25.2 65.9,25.18 65.9,24.78 65.07,23.95 65.07,22.45
N9537951 on BOTTOM: 38.96,27.53 42.57,27.53 42.95,27.15 42.95,25.43 42.67,25.15 40.82,25.15 39.95,26.01 39.04,26.01 38.58,26.47 38.58,27.15
N9537951 on BOTTOM: 69.62,37.69 70.28,37.03 70.28,34.95 69.85,34.52 69.85,30.58 68.4,29.13 57.1,29.13 55.09,27.13 55.09,19.96 52.96,17.83 52.55,17.83 52.1,18.29 52.1,28.35 51,29.44 45.67,29.44 44.5,30.61 29.87,30.61 28.75,31.72 28.75,37.01 29.44,37.69
N9537951 on BOTTOM: 23.37,3.63 23.37,1.17 24.41,0.13 54.56,0.13 54.89,0.46 54.89,1.7 53.44,3.15 25.98,3.15 24.87,4.27 24,4.27
N9537951 on BOTTOM: 70.1,36.65 70.82,36.65 71.09,36.37 70.82,36.09 71.09,35.81 70.82,35.53 71.09,35.26 70.82,34.98 70.1,34.98
N9538078 on BOTTOM: 25.88,24.74 24.77,25.86 24.77,28.4 25.5,29.13 25.91,29.13 25.96,29.08 28.91,29.08 32.28,25.7 35.51,25.7 35.71,25.5 35.71,21.44 35.56,21.29 31.29,21.29 30.73,20.73 30.73,18.11 30.63,18.01 26.44,18.01 25.88,18.57
N9539529 on BOTTOM: 5.11,11.96 5.11,10.95 4.29,10.13 0.64,10.13 0.15,10.62 0.15,18.06 0.69,18.59 2.24,18.59 2.74,18.08 2.74,14.3 2.95,14.1 2.97,14.1
N9539533 on BOTTOM: 10.36,20.52 10.36,14.25 12.32,12.29 12.32,10.19 12.78,9.73 14.05,9.73 14.45,10.13 14.45,13.26 13.21,14.5 13.21,19.48 12.17,20.52
N9539533 on BOTTOM: 11.61,21.03 11.89,21.31 12.17,21.03 12.17,20.32 10.49,20.32 10.49,21.03 10.77,21.31 11.05,21.03 11.33,21.31
N9539579 on BOTTOM: 18.2,16.57 18.2,14.19 15.54,11.53 15.54,10.26 15.95,9.86 18.06,9.86 22.5,14.3 22.5,15.62 16.97,21.16 16.97,21.72 15.93,22.76 13.92,22.76 13.87,22.71 13.87,20.9
N9539579 on BOTTOM: 15.09,23.06 15.37,23.34 15.65,23.06 15.65,22.35 13.97,22.35 13.97,23.06 14.25,23.34 14.53,23.06 14.81,23.34
N9541022 on BOTTOM: 10.49,22.76 12.17,22.76 12.17,22.05 11.89,21.77 11.61,22.05 11.33,21.77 11.05,22.05 10.77,21.77 10.49,22.05
N9541022 on BOTTOM: 6.53,26.39 7.98,24.94 10.44,24.94 12.14,23.24 12.14,22.58 6.5,22.58 3.84,25.25 1.14,25.25 0.3,26.09 0.3,29.51 0.99,30.2 5.79,30.2 6.53,29.46
N9541042 on BOTTOM: 13.97,24.79 15.65,24.79 15.65,24.08 15.37,23.8 15.09,24.08 14.81,23.8 14.53,24.08 14.25,23.8 13.97,24.08
N9541042 on BOTTOM: 8.94,29.87 14,29.87 15.7,28.17 15.7,24.77 15.6,24.66 13.36,24.66 12.57,25.45 12.57,26.24 12.19,26.62 9.12,26.62 8.89,26.85 8.89,27.76 8.86,27.79 8.86,29.79
N9541964 on TOP: 33.78,11.51 33.78,4.32 33.99,4.11 35.18,4.11 35.51,4.45 35.51,11.33 35.05,11.79 34.06,11.79
N9541964 on TOP: 58.17,3.86 63.7,3.86 64.85,2.72 64.85,0.28 64.69,0.13 58.09,0.13 57.84,0.38 57.84,3.53
N9541964 on BOTTOM: 64.69,2.82 63.91,3.61 59.86,3.61 58.2,1.96 58.2,0.06 58.24,0.03 78.77,0.03 79.17,0.43 79.17,2.54 78.87,2.84 71.91,2.84 71.88,2.82
N9541964 on BOTTOM: 39.6,10.06 39.73,10.19 39.73,12.62 39.62,12.73 36.09,12.73 35.56,13.26 35.56,18.26 33.48,18.26 33.45,18.29 33.2,18.29 33.2,10.52 33.66,10.06
N9542431 on BOTTOM: 33.55,27.53 33.55,28.98 34.1,29.53 43.5,29.53 45.21,27.81 50.6,27.81 50.67,27.74 50.67,26.24 50.65,26.21 45.59,26.21 43.04,28.77 37.11,28.77 35.75,27.41 33.78,27.41 33.76,27.38 33.71,27.38
N9542586 on TOP: 23.67,17.6 26.97,17.6 27.25,17.32 27.25,14.99 25.76,13.49 23.32,13.49 23.27,13.54 23.27,17.2
N9542586 on BOTTOM: 23.41,16.09 23.93,16.61 26.52,16.61 26.54,16.64 30.61,16.64 30.84,16.41 30.84,14.22 30.15,13.54 23.44,13.54 23.41,13.58
N9542750 on TOP: 27.15,5.44 27.48,5.77 27.48,8.15 27.2,8.43 23.85,8.43 23.84,8.42 23,8.42 22.73,8.15 22.73,5.69 22.99,5.44
N9542750 on TOP: 61.9,10.41 61.9,6.43 62.31,6.02 64.34,6.02 65.33,7.01 65.33,10.19 64.82,10.69 62.18,10.69
N9542750 on TOP: 43.51,10.69 45.39,10.69 45.85,10.24 45.85,9.25 45.54,8.94 43.56,8.94 43.33,9.17 43.33,10.52
N9542750 on BOTTOM: 44.35,10.77 45.21,10.77 47.19,8.79 60.96,8.79 62.03,9.86 63.93,9.86 64.41,9.37 64.41,8 64.69,7.72 70.61,7.72 70.89,7.44 70.89,4.6 70.87,4.57 65.25,4.57 64.54,5.28 63.09,5.28 60.6,7.77 43.33,7.77 42.81,7.25 34.14,7.25 31.56,4.67 26.82,4.67 25.73,5.77 24,5.77 23.47,6.3 23.47,8.1 23.72,8.36 25.6,8.36 25.63,8.38 25.73,8.28 42.42,8.28 43.81,9.68 43.81,10.24
N9542850 on BOTTOM: 65.28,11.56 67.97,11.56 69.06,12.65 73.51,12.65 73.81,12.34 73.81,7.29 72.06,7.29 71.88,7.47 71.88,8.48 71.49,8.88 71.48,8.86 65.28,8.86 65.18,8.97 65.18,11.46
N9544139 on TOP: 46.99,15.85 48.46,15.85 48.67,15.65 48.67,14.3 48.46,14.1 46.96,14.1 46.71,14.35 46.71,15.57
N9544139 on TOP: 69.29,27.18 70.1,26.37 70.99,26.37 71.32,26.7 71.32,27.64 70.59,28.37 69.62,28.37 69.29,28.04
N9544139 on BOTTOM: 47.12,15.72 51.71,15.72 55.75,19.76 55.75,26.34 57.68,28.27 70.69,28.27 71.37,27.58 71.37,26.67 71.07,26.37 70.28,26.37 69.72,26.92 58.42,26.92 56.54,25.04 56.54,19.02 51.87,14.35 47.12,14.35 46.86,14.61 46.86,15.47
N9545267 on BOTTOM: 66.09,23.67 69.27,23.67 69.34,23.6 69.34,20.27 69.09,20.02 67.84,20.02 67.56,20.29 65.48,20.29 65.48,21.64 66.09,22.25
N9545282 on TOP: 61.95,14.97 61.95,13.34 62.46,12.83 65.25,12.83 65.51,13.08 65.51,15.14 65.09,15.56 62.53,15.56
N9545282 on BOTTOM: 61.9,14.96 61.9,13.39 62.46,12.83 66.95,12.83 66.95,14.17 66.93,14.2 65.2,14.2 63.75,15.65 62.59,15.65
N9545292 on BOTTOM: 65.33,15.21 65.33,19.41 65.46,19.53 66.73,19.53 66.9,19.35 66.9,15.09 65.46,15.09
N9546383 on TOP: 114.99,9.93 116.61,8.31 116.61,5.84 117.81,4.65 122.33,4.65 122.94,4.04 122.94,0.38 122.69,0.14 97.17,0.14 96.27,1.04 96.27,9.12 97.08,9.93
N9546383 on BOTTOM: 105.23,9.91 116.76,9.91 117.32,9.35 117.32,6.93 118.52,5.74 121.18,5.74 122.17,4.75 123.67,4.75 123.8,4.62 123.8,1.45 122.48,0.13 97.21,0.13 96.27,1.07 96.27,8.1 97.16,8.99 104.32,8.99
N9546628 on BOTTOM: 103.28,9.78 103.56,10.06 103.56,13.49 103.4,13.64 99.75,13.64 99.67,13.56 99.67,10.08 99.97,9.78
N9547867 on TOP: 81.43,37.82 129.01,37.82 131.47,35.36 131.47,33.73 131.11,33.38 128.88,33.38 128.42,33.83 128.42,36.42 127.66,37.19 85.52,37.19 80.34,32 79.1,32 78.26,32.84 78.28,32.87 78.28,34.67
N9547867 on BOTTOM: 123.04,32.92 122.86,32.74 120.09,32.74 119.58,32.23 115.7,32.23 115.42,32.51 115.42,36.98 116.41,37.97 132.99,37.97 133.22,37.74 133.22,33.02 133.12,32.92
N9547867 on BOTTOM: 88.32,30.45 88.32,30.12 88.98,29.46 90.78,29.46 90.78,30.23 90.75,30.25 89.18,30.25 88.77,30.66 88.52,30.66
N9547867 on BOTTOM: 78.08,32.23 79.76,32.23 80.09,32.56 80.09,36.73 79.96,36.86 77.85,36.86 77.67,36.68 77.67,32.64
N9547867 on BOTTOM: 77.93,34.97 77.22,34.97 76.94,35.25 77.22,35.53 76.94,35.81 77.22,36.09 76.94,36.37 77.22,36.65 77.93,36.65
N9549268 on BOTTOM: 71.96,6.3 71.96,4.22 72.19,3.99 78.92,3.99 78.92,6.15 78.87,6.2 78.87,9.96 77.24,11.58 75.39,11.58 75.18,11.38 75.18,6.73 75.21,6.71 75.03,6.53 72.19,6.53
N9550559 on TOP: 43.56,17.07 45.34,17.07 45.72,16.69 45.72,15.85 45.29,15.42 43.84,15.42 43.46,15.8 43.46,16.97
N9550559 on BOTTOM: 43.94,15.67 43.94,18.77 44.07,18.9 45.21,18.9 45.62,18.49 45.62,15.77 45.24,15.39 44.22,15.39
N9550563 on TOP: 66.27,27.36 66.27,26.72 69.19,23.8 71.32,23.8 71.4,23.88 71.4,25.15 71.25,25.3 69.55,25.3 67.26,27.58 66.5,27.58
N9550563 on BOTTOM: 69.43,25.64 69.72,25.35 71.17,25.35 71.37,25.15 71.37,22.4 70.1,22.4 70.08,22.43 70.08,23.98 69.7,24.36 67.88,24.36 67.86,24.38 67.86,25.57 67.93,25.64
N9550563 on BOTTOM: 41.71,14.91 41.71,18.92 43.13,18.92 43.13,14.88 43.1,14.86 41.76,14.86
N9560533 on TOP: 46.69,19.05 46.79,19.15 48.84,19.15 48.97,19.02 48.97,16.87 48.64,16.54 46.79,16.54 46.69,16.64
N9560533 on BOTTOM: 46.89,18.69 50.72,18.69 50.72,17.07 50.29,16.64 46.84,16.64 46.76,16.71 46.76,18.57
N9561535 on TOP: 23.24,9.5 22.81,9.93 22.81,11.99 23.11,12.29 27.51,12.29 27.58,12.22 27.58,9.8 27.28,9.5
N9561535 on BOTTOM: 30.7,12.31 31.19,11.81 31.19,10.36 30.53,9.7 23.6,9.7 23.29,10.01 23.29,11.66 23.94,12.31
N14039798 on BOTTOM: 0.41,5.31 5.08,5.31 9.25,1.14 16.79,1.14 17.93,2.29 17.93,3.12 15.6,5.46 15.6,6.73 15.98,7.11 19.68,7.11 20.65,6.15 20.65,0.44 20.29,0.09 11.8,0.09 11.79,0.08 0.2,0.08 0.13,0.15 0.13,5.03
N14052600 on TOP: 9.26,11.14 9.26,7.18 13.53,2.92 14.81,2.92 15.24,3.35 15.24,3.38 15.29,3.43 15.29,4.27 14.58,4.98 14.58,6.12 13.46,7.24 12.22,7.24 10.87,8.59 10.87,11.4 7.8,14.48 7.8,18.49 7.59,18.69 6.25,18.69 5.85,18.29 5.85,14.56
N14052600 on BOTTOM: 5.69,18.62 5.69,16.87 6.02,16.54 7.52,16.54 8.13,17.14 8.13,18.72 7.95,18.9 7.77,18.9 7.67,19 6.07,19
N14052600 on BOTTOM: 12.42,6.6 12.42,3.81 13.39,2.84 14.68,2.84 15.13,3.29 15.13,4.37 14.55,4.94 14.55,6.38 13.93,7 12.81,7
N14052856 on BOTTOM: 49.15,24.51 49.15,20.42 49.12,20.4 49.17,20.35 50.67,20.35 50.67,24.51
N14062269 on BOTTOM: 69.98,21.01 69.98,18.16 70.13,18.01 71.25,18.01 71.48,18.24 71.48,20.8 71.09,21.18 70.15,21.18
N14069124 on BOTTOM: 37.19,20.5 37.19,14.45 37.31,14.33 39.6,14.33 39.7,14.43 39.7,20.37 39.55,20.52 37.21,20.52
N14069146 on BOTTOM: 37.24,22.17 37.57,21.84 42.67,21.84 42.85,22.02 42.85,23.34 42.16,24.03 40.01,24.03 39.55,24.49 39.55,24.84 39.47,24.92 37.34,24.92 37.24,24.82
N14074284 on BOTTOM: 112.47,31.14 112.75,30.86 112.75,29.49 112.62,29.36 110.95,29.36 110.01,30.3 110.01,30.84 110.31,31.14
N14074284 on BOTTOM: 89.36,21.79 89.36,21.39 88.49,20.52 86.39,20.52 86.08,20.83 84.86,20.83 84.81,20.78 84.81,19.58 84.84,19.56 86.13,19.56 86.54,19.96 89.08,19.96 89.1,19.94 90.2,19.94 90.73,20.47 90.73,21.59 91.39,22.25 91.39,24.28 92.56,25.45 92.56,26.97 93.01,27.43 93.01,28.6 92.76,28.85 92.02,28.85 91.74,28.57 91.74,27.56 92.05,27.25 92.05,25.65 91.31,24.92 90.4,24.92 90.25,24.77 90.25,24.59 90.63,24.21 90.63,22.71 90.17,22.25 89.81,22.25
N14074284 on BOTTOM: 122.66,22.56 122.66,23.32 124.51,25.17 128.98,25.17 129.39,24.77 129.39,23.6 128.85,23.06 127.23,23.06 127.15,23.14 124.84,23.14 124.21,22.5 122.71,22.5
N14074308 on BOTTOM: 86.61,35.23 86.61,36.09 87.45,36.93 93.22,36.93 93.95,36.2 93.95,35.2 93.93,35.18 93.09,35.18 93.04,35.23 93.04,35.97 92.43,36.58 89.76,36.58 88.32,35.13 86.72,35.13
N14074340 on BOTTOM: 86.64,34.52 87.93,34.52 89.05,33.4 89.05,32.66 89.53,32.18 92.28,32.18 93.07,31.39 93.07,30.15 92.99,30.07 91.74,30.07 91.74,30.84 91.52,31.06 88.85,31.06 88.72,31.19 88.72,31.32 88.34,31.7 88.34,33.22 87.86,33.71 86.66,33.71 86.64,33.73
N14074422 on BOTTOM: 89.74,33.25 89.74,35.38 90.55,36.2 91.95,36.2 92.23,35.92 92.23,35.1 92.58,34.75 94.23,34.75 94.59,35.1 94.59,35.74 95.68,35.74 95.78,35.64 95.78,34.92 95.35,34.49 92.15,34.49 91.82,34.82 91.06,34.82 90.6,34.37 90.6,33.22 89.76,33.22
N14074628 on BOTTOM: 97.87,32.82 99.64,32.82 99.69,32.77 99.69,32.03 99.59,31.93 98.12,31.93 97.76,32.28 97.76,32.72
N14074640 on BOTTOM: 95.4,25.2 93.78,25.2 93.45,25.53 93.45,29.62 93.88,30.05 93.88,31.19 95.58,31.19 96.04,31.65 96.04,32.69 97.43,34.09 97.46,34.09 98.2,34.82 101.88,34.82 102.44,34.26 102.44,32.77 102.21,32.54 100.81,32.54 100.03,33.32 97.82,33.32 96.93,32.44 96.93,30.89 95.07,29.03 94.34,29.03 93.88,28.57 93.88,25.73 94.08,25.53 95.35,25.53 95.43,25.45 95.43,25.22
N14074656 on TOP: 128.7,9.37 128.68,9.37 127.81,8.51 127.81,7.42 128.96,6.27 130.23,6.27 131.98,8.03 131.98,10.26 131.39,10.85 130.18,10.85
N14074656 on BOTTOM: 92.15,34.04 95.81,34.04 97.89,36.12 99.21,36.12 99.29,36.04 99.29,35.71 99.16,35.59 98.17,35.59 95.5,32.92 95.5,32.89 95.2,32.59 95.2,32.05 94.16,32.05 93.45,32.77 92.23,32.77 92.15,32.84
N14074656 on BOTTOM: 125.83,10.57 132.87,10.57 133.22,10.21 133.22,6.43 133.12,6.32 128.78,6.32 128.14,5.69 126.16,5.69 125.54,6.31 125.54,10.27
N14074980 on BOTTOM: 89.28,28.8 90.83,28.8 91.26,28.37 91.26,27.76 91.11,27.61 90.88,27.61 90.47,28.02 89.53,28.02 89.26,28.3 89.26,28.78
N14074984 on BOTTOM: 84.58,29.82 84.58,27.25 84.61,27.23 86.31,27.23 86.51,27.03 86.51,25.12 86.54,25.1 87.48,25.1 87.58,25.2 87.58,25.22 87.86,25.5 87.86,26.14 88.11,26.39 88.14,26.39 88.14,26.8 88.04,26.9 87.86,26.9 87.58,27.18 87.58,27.56 87.48,27.66 85.93,27.66 85.55,28.04 85.55,29.82
N14075000 on BOTTOM: 84.58,31.24 85.67,31.24 86.03,30.89 87.48,30.89 87.66,30.71 87.66,29.59 88.57,28.68 88.57,28.07 88.93,27.71 88.93,27.23 88.85,27.15 88.39,27.15 87.93,27.61 87.93,28.02 87.68,28.27 86.69,28.27 86.41,28.55 86.41,30.25 86.23,30.43 84.58,30.43
N14077546 on BOTTOM: 123.22,18.77 123.22,17.48 123.49,17.2 124.97,17.2 125.37,16.79 125.37,15.37 125.53,15.21 131.22,15.21 132.05,16.05 132.05,22.1 131.7,22.45 124.87,22.45 124.82,22.4 124.82,21.51 125.6,20.73 128.17,20.73 128.42,20.47 128.42,18.24 128.02,17.83 125.43,17.83 124.76,18.49 124.76,18.8 123.24,18.8
N14077592 on BOTTOM: 121.26,19 121.26,20.24 121.27,20.26 121.27,20.92 121.89,21.54 123.67,21.54 125.2,20.02 127.94,20.02 128.02,19.94 128.02,18.67 127.81,18.47 125.96,18.47 124.55,19.88 123.15,19.88 123.14,19.89 123.09,19.89 122.68,19.48 122.68,18.52 122.66,18.49 121.28,18.49 121.23,18.54 121.23,18.97
N14078876 on TOP: 77.6,25.37 79.43,25.37 79.55,25.25 79.55,23.8 77.6,23.8 77.57,23.77 77.52,23.83 77.52,25.3
N14078876 on BOTTOM: 77.55,25.32 77.55,22.25 82.42,17.37 86.11,17.37 86.11,18.59 84.84,18.59 84.73,18.49 82.68,18.49 79.43,21.74 79.43,24.94 79.04,25.32
N14079186 on TOP: 77.6,27.71 77.6,26.64 77.93,26.31 79.15,26.31 79.73,26.9 79.73,27.76 79.48,28.02 77.9,28.02
N14079186 on BOTTOM: 77.61,26.61 78,26.21 79.55,26.21 80.09,25.68 80.09,21.92 82.89,19.11 84.06,19.11 84.33,19.38 84.33,20.22 83.85,20.7 82.07,20.7 80.87,21.89 80.87,26.62 79.65,27.84 77.75,27.84 77.61,27.7
N14079186 on BOTTOM: 89.46,19.48 90.47,18.47 90.47,16.59 90.98,16.08 94.49,16.08 95.22,16.81 95.22,19.35 95.45,19.58 96.77,19.58 96.77,17.53 94.77,15.52 88.65,15.52 87.2,16.97 87.2,18.26 86.46,19 86.46,19.18 86.77,19.48
N14082476 on BOTTOM: 82.7,23.47 85.85,23.47 86.36,23.98 86.36,24.51 87.38,24.51 87.48,24.41 87.48,23.98 87.85,23.61 87.97,23.61 88.04,23.55 88.06,23.55 88.11,23.5 88.11,23.16 87.6,22.66 82.8,22.66 82.7,22.76
N14152194 on BOTTOM: 84.58,26.59 84.58,24.13 84.63,24.08 85.55,24.08 85.57,24.1 85.57,26.52 85.47,26.62 84.61,26.62
N14168566 on BOTTOM: 125.37,14.76 125.37,12.09 125.63,11.84 128.45,11.84 129.08,12.47 129.08,14.25 128.63,14.71 125.43,14.71
N14175933 on BOTTOM: 96.55,28.47 96.55,29.67 98.2,31.32 101.22,31.32 101.65,30.89 101.65,29.36 100.15,29.36 99.77,28.98 99.77,28.32 99.75,28.3 98.4,28.3 98.25,28.45 96.57,28.45
N14177524 on BOTTOM: 94.34,25.96 94.34,27 95.15,27.81 97.54,27.81 97.54,27 96.55,27 96.52,27.03 96.14,27.03 95.73,26.62 95.73,25.93 95.63,25.83 94.46,25.83
N14180613 on BOTTOM: 94.49,22.94 95.55,22.94 96.24,22.25 98.17,22.25 98.6,21.82 98.6,21.03 95.86,21.03 94.36,22.53 94.36,22.81
N14180712 on BOTTOM: 107.87,26.06 107.67,26.26 106.1,26.26 106.1,27.56 106.2,27.66 107.8,27.66 108.36,27.1 108.36,26.21 108.2,26.06
N14180712 on BOTTOM: 91.29,16.59 93.95,16.59 94.49,17.12 94.49,21.67 93.9,22.25 93.75,22.25 93.68,22.17 93.68,18.52 93.22,18.06 91.49,18.06 91.29,17.86
N14180712 on BOTTOM: 96.57,24.59 96.57,23.83 96.67,23.72 97.56,23.72 97.76,23.93 97.76,24.56 97.74,24.59
N14181517 on BOTTOM: 81.86,27.23 83.54,27.23 83.59,27.28 83.59,28.14 83.57,28.17 81.99,28.17 81.69,27.86 81.69,27.41
N14181517 on BOTTOM: 87.86,22.05 88.72,22.91 89.97,22.91 89.97,22.66 89.84,22.53 89.43,22.53 88.52,21.62 88.52,21.26 88.47,21.21 87.02,21.21 87,21.18 86.49,21.18 86.39,21.29 86.39,21.92 86.51,22.05
N14182326 on BOTTOM: 82.65,26.67 82.65,24.18 82.73,24.1 83.67,24.1 83.67,26.57 83.57,26.67
N14183243 on BOTTOM: 100.38,24.31 100.38,25.02 101.78,26.42 104.14,26.42 104.27,26.54 105.18,26.54 105.26,26.47 105.26,25.76 105.16,25.65 104.19,25.65 104.06,25.78 102.29,25.78 101.4,24.89 101.4,24.33 101.35,24.28 100.41,24.28
N14183547 on BOTTOM: 98.2,23.7 103.23,23.7 103.25,23.72 103.25,22.86 103,22.61 101.3,22.61 100.46,21.77 100.46,21.06 99.57,21.06 99.52,21.11 99.52,22.23 98.91,22.83 96.88,22.83 96.85,22.86 96.85,23.16 96.93,23.24 97.74,23.24
N14184679 on BOTTOM: 97.61,20.42 100.48,20.42 100.48,19.61 100.23,19.35 97.87,19.35 97.61,19.61
N14215361 on BOTTOM: 69.42,14.53 71.3,14.53 71.42,14.66 71.42,15.72 71.41,15.74 71.41,15.91 71.2,16.13 69.93,16.13 69.27,16.79 69.27,19.08 69.14,19.2 67.84,19.2 67.84,16.1
N14231123 on BOTTOM: 109.17,28.3 110.57,28.3 110.77,28.5 112.55,28.5 112.75,28.3 112.75,27.13 112.5,26.87 109.17,26.87 109.09,26.95 109.09,28.22

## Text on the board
Ref Des/Silkscreen Top: DER-1102 Rev D | 2604 | S/N | DIM | LED | DER-1102 | Rev D | +
User.6: NOTES: UNLESS OTHERWISE SPECIFIED | 1.  THROUGH HOLES ARE PLATED THROUGH. | EXCEPTIONS WILL BE NOTED IN DRILL CHART "NOTE". | 2.  MATERIAL: BASE MATERIAL LAMINATED EPOXY | UL APPROVED MANUFACTURED SOURCE FOR FR4. | 3.  SOLDER PLATE WILL BE RoHS COMPLIANT. | 4.  SOLDER MASK LPI (LIQUID PHOTO IMAGEABLE) BOTH SIDES. COLOR GREEN. | SOLDER MASK (REGISTRATION) -0/+0.003" | 5.  SILKSCREEN TOP/BOTTOM SIDE. COLOR WHITE. (MIN.WIDTH 0.005" MAX.WIDTH 0.010") | 6.  FINISH TO BE SMOBC. | 7.  LF HASL. | 8.  BOARD DIMENSION +/- 0.005" | 9.  DRILL TOLERANCE +/- 0.003" | 10. TRACE WIDTH UNDER 0.010" +/- 0.002" | TRACE WIDTH OVER 0.011" +/- 0.005" | 11. TRACE SPACE +/- 0.003" | 12. MATERIAL FR4 COPPER 2 OZ BOARD THICKNESS 0.062" | DELETE THESE HOLES:
User.9: FIGURE | FINISHED_SIZE | 12.0 | 20.0 | 25.0 | 28.0 | 30.0 | 35.0 | 40.0 | 50.0 | 51.0 | 52.0 | 55.0 | DRILL CHART: TOP to BOTTOM | ALL UNITS ARE IN MILS | TOLERANCE_DRILL | +0.0/-0.0 | +3.0/-3.0 | PLATED | QTY | 373 | 9 | 2 | 4 | 6 | 3 | 19 | 1
